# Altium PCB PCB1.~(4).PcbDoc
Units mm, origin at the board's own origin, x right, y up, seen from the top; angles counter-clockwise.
Board outline 77.6 x 45.97 mm, 2 copper layers (Top Layer, Bottom Layer); 10 components, 6 nets, 87 pads, 0 vias.
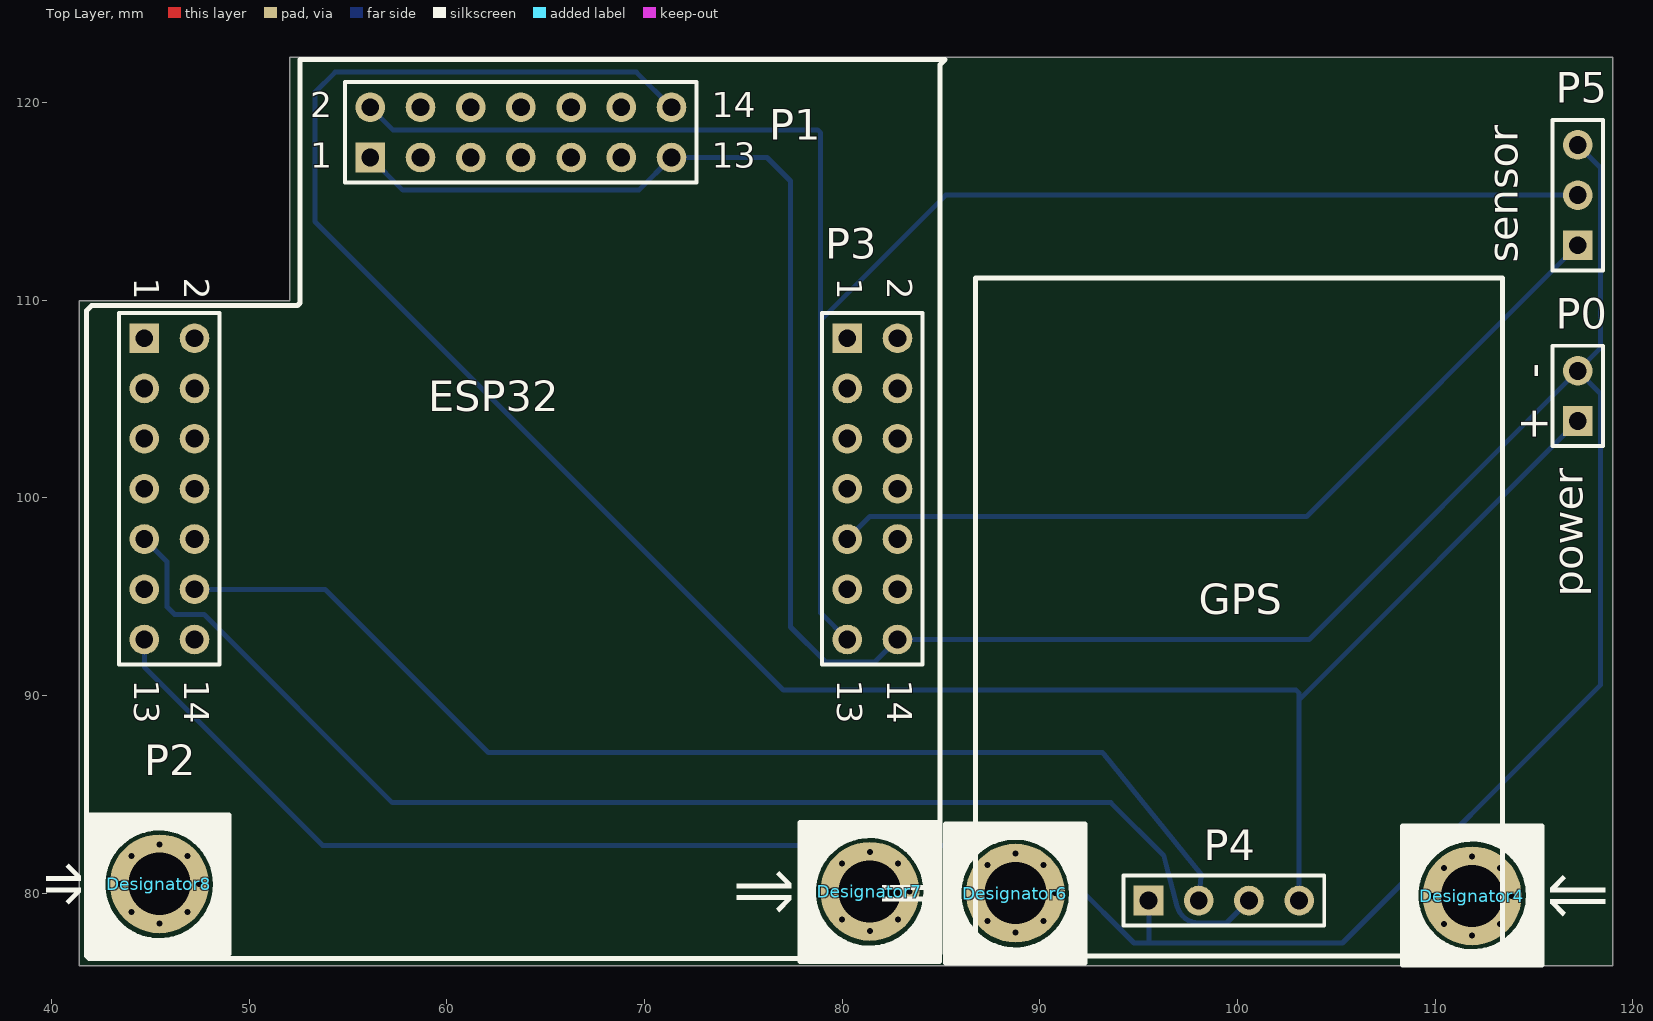
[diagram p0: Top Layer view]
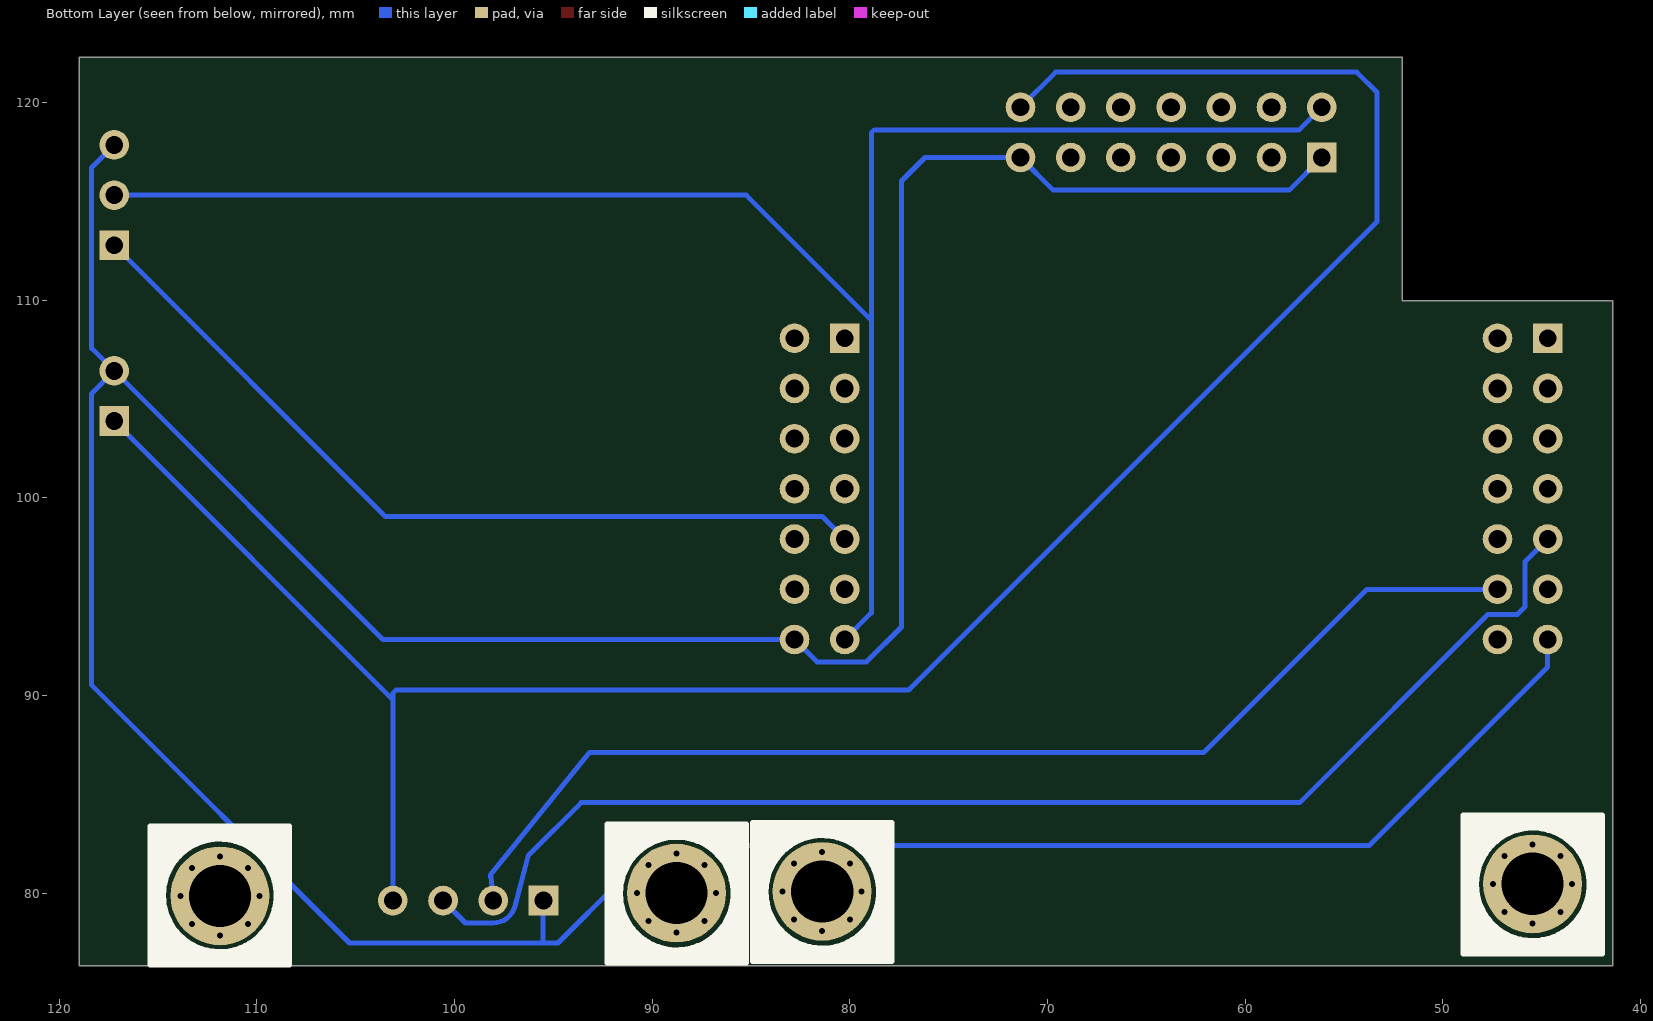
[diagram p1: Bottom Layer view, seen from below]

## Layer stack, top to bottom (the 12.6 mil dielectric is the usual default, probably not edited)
Top Solder: solder mask 0.0102, Solder Resist, Dk 3.5
Top Layer: signal copper 0.0356
Dielectric 1: dielectric 0.32, FR-4, Dk 4.8
Bottom Layer: signal copper 0.0356
Bottom Solder: solder mask 0.0102, Solder Resist, Dk 3.5

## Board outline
41.402,76.327 41.402,109.982 52.07,109.982 52.07,122.301 118.999,122.301 118.999,76.327

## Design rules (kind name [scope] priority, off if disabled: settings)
Clearance [All] p1: gap=0.254 ignorepadtopadclearanceinfootprint=FALSE
PolygonConnect [All] p1: connectstyle=Relief reliefconductorwidth=0.254 reliefentries=4 polygonreliefangle="90 Angle" airgapwidth=0.254
RoutingVias [All] p1: holewidth=0.711 width=1.27 viastyle="Through Hole" minholewidth=0.711 minwidth=1.27 maxholewidth=0.711 maxwidth=1.27
SolderMaskExpansion [All] p1: expansion=0.102 istentingtop=FALSE
SupplyNets "Schematic Supply Nets_2" [InNet('VCC')] p1: voltage=0.000
SupplyNets "Schematic Supply Nets_1" [InNet('GND')] p2: voltage=0.000
SupplyNets "Schematic Supply Nets" [InNet('3.3v')] p3: voltage=0.000
Width [All] p1: maxlimit=0.254 minlimit=0.254 preferedwidth=0.254
30 further rules are at their usual default settings.

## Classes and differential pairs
component class Sheet1: P0 P1 P2 P3 P4 P5

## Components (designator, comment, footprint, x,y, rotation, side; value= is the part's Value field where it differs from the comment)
Designator4 "Comment" "Board Screw" 111.87,79.866 r90 top
Designator6 "Comment" "Board Screw" 88.773,80.01 r270 top
Designator7 "Comment" "Board Screw" 81.407,80.093 r270 top
Designator8 "Comment" "Board Screw" 45.466,80.474 r270 top
P0 "Header 2" HDR1X2 117.221,103.886 r90 top
P1 "Header 7X2" HDR2X7 56.134,117.221 r0 top
P2 "Header 7X2" HDR2X7 44.704,108.077 r270 top
P3 "Header 7X2" HDR2X7 80.264,108.077 r270 top
P4 "Header 4" HDR1X4 95.504,79.629 r0 top
P5 "Header 3" HDR1X3 117.221,112.776 r90 top

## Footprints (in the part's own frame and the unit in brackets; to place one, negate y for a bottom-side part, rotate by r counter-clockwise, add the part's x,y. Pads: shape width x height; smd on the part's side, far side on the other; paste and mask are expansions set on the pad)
"Board Screw" [mm]
  round 0.6 hole 0.3: S(-2,0) S(-1.414,-1.414) S(-1.414,1.414) S(0,2) S(0,-2) S(1.414,-1.414) S(1.414,1.414) S(2,0)
  round 5 hole 3.15 mask+0.1: S(0,0)
  silkscreen extent -3.49,-6.75 3.56,3.52, body extent -2.67,-2.64 2.69,2.72, height 2.34
HDR1X2 [mm] "Connector; Header; 2 Position"
  rect 1.5x1.5 hole 0.9: 1(0,0)
  round 1.5 hole 0.9: 2(2.54,0)
  silkscreen extent -1.27,-1.27 3.81,1.27, body extent -1.27,-1.28 3.81,1.26, height 8.79
HDR1X3 [mm] "Connector; Header; 3 Position"
  rect 1.5x1.5 hole 0.9: 1(0,0)
  round 1.5 hole 0.9: 2(2.54,0) 3(5.08,0)
  silkscreen extent -1.27,-1.27 6.35,1.27, body extent -1.26,-1.27 6.36,1.27, height 8.38
HDR1X4 [mm] "Connector; Header; 4 Position"
  rect 1.5x1.5 hole 0.9: 1(0,0)
  round 1.5 hole 0.9: 2(2.54,0) 3(5.08,0) 4(7.62,0)
  silkscreen extent -1.27,-1.27 8.89,1.27, body extent -1.27,-1.28 8.89,1.26, height 8.38
HDR2X7 [mm] "Connector; Header; 7x2 Position"
  rect 1.5x1.5 hole 0.9: 1(0,0)
  round 1.5 hole 0.9: 2(0,2.54) 3(2.54,0) 4(2.54,2.54) 5(5.08,0) 6(5.08,2.54) 7(7.62,0) 8(7.62,2.54) 9(10.16,0) 10(10.16,2.54) 11(12.7,0) 12(12.7,2.54) 13(15.24,0) 14(15.24,2.54)
  silkscreen extent -1.27,-1.27 16.51,3.81

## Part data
P0: "Header, 2-Pin"
P1 P2 P3: "Header, 7-Pin, Dual row"
P4: "Header, 4-Pin"
P5: "Header, 3-Pin"

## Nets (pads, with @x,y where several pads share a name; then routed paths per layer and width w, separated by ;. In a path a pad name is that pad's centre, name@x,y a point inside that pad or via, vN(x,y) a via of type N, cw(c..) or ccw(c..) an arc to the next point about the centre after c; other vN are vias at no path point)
3.3v: P1.2 P3.13 P5.2 | length 90.4
  Bottom Layer w0.254: P1.2 57.277,118.618 78.769,118.618 78.918,118.469 78.918,108.991 ; P3.13 78.918,94.183 78.918,108.991 ; P5.2 85.242,115.316 78.918,108.991
GND: P0.2 P1.1 P1.13 P2.13 P3.14 P4.1 P5.3 | length 210.4
  Bottom Layer w0.254: P2.13 44.704,91.44 53.721,82.423 79.712,82.423 cw(c81.407,80.093) 83.102,82.423 87.199,82.423 cw(c88.773,80.01) 91.575,80.681 91.624,80.631 94.774,77.482 102.027,77.482 105.32,77.482 118.364,90.526 118.364,105.283 P0.2 ; P1.1 57.785,115.57 69.723,115.57 P1.13 76.2,117.221 77.394,116.027 77.394,93.472 79.172,91.694 81.661,91.694 P3.14 103.632,92.837 P0.2 ; 95.521,77.565 P4.1@95.521,79.978 ; P5.3 118.364,116.713 118.364,107.569 P0.2
rx: P2.12 P4.2 | length 58.6
  Bottom Layer w0.254: P2.12 53.848,95.377 62.109,87.116 93.171,87.116 93.255,87.032 98.173,80.928 98.173,80.825 98.171,80.812 P4.2
"signal finger": P3.9 P5.1 | length 43.1
  Bottom Layer w0.254: P3.9 81.407,99.06 103.505,99.06 P5.1
tx: P2.9 P4.3 | length 66.7
  Bottom Layer w0.254: P2.9 45.847,96.774 45.847,94.488 46.228,94.107 47.727,94.107 57.252,84.582 93.599,84.582 96.274,81.907 96.95,79.341 ccw(c98.044,79.629) 98.044,78.498 99.453,78.498 P4.3
VCC: P0.1 P1.14 P4.4 | length 115.8
  Bottom Layer w0.254: P1.14 69.596,121.539 54.356,121.539 53.34,120.523 53.34,113.97 77.038,90.272 102.975,90.272 103.124,90.123 103.124,89.789 ; P4.4 103.124,89.789 ; P0.1 103.124,89.789
pads on no net: Designator4.S Designator6.S Designator7.S Designator8.S P1.3 P1.4 P1.5 P1.6 P1.7 P1.8 P1.9 P1.10 P1.11 P1.12 P2.1 P2.2 P2.3 P2.4 P2.5 P2.6 P2.7 P2.8 P2.10 P2.11 P2.14 P3.1 P3.2 P3.3 P3.4 P3.5 P3.6 P3.7 P3.8 P3.10 P3.11 P3.12

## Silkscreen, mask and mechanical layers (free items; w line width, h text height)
Top Overlay:
  lines w0.254: 41.783,76.835 41.783,109.474 42.037,109.728 52.451,109.728 52.578,109.855 52.578,122.174 85.217,122.174 84.963,121.92 84.963,76.962 84.709,76.708 41.91,76.708 41.783,76.835 ; 86.741,76.835 113.411,76.835 113.411,111.125 86.741,111.125 86.741,76.835
  text "sensor" at 114.173,111.887 h1.52 r90
  text "-" at 115.697,106.045 h1.52 r90
  text "ESP32" at 59.055,104.394 h1.52
  text "+" at 115.697,102.87 h1.52 r90
  text "power" at 117.475,94.996 h1.52 r90
  text "GPS" at 98.044,94.107 h1.52
Mechanical 1:
  the board outline again, w0.254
